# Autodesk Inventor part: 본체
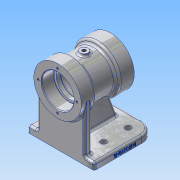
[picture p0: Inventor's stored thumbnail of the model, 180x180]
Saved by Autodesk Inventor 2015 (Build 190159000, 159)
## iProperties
Created: 2020-06
Part Number: 본체
Material: 알루미늄 6061
Document SubType Name: Modeling
Designer: user
Density: 2.7 g/cm^3
Appearance: 알루미늄 - 평지
Author: user
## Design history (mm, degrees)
sketch "스케치1"
  geometry: L1 (0, 49)-(90, 49); L2 (90, 49)-(90, -49); L3 (90, -49)-(0, -49); L4 (0, -49)-(0, 49); 2 further points
  constraints: 8 end point, 2 parallel, 1 coincident, 1 horizontal, 1 midpoint, 1 perpendicular
  dimensions: "d0" = 90 distance of L1.start L1.end; "d1" = 98 distance of L1.end L2.end
extrude "돌출1" new body sketch "스케치1" distance "d2" = 10; taper "d3" = 0 deg
sketch "스케치2"
  geometry: L1 (0, 0)-(-90, 0) reference; L2 (5, 80)-(-73, 80); L3 (0, 0)-(0, 10) reference; L4 (5, 80)-(-17, 80); L5 (-17, 80)-(-17, 115); L6 (-17, 115)-(5, 115); L7 (5, 115)-(5, 80); L8 (-73, 80)-(-51, 80); L9 (-51, 80)-(-51, 115); L10 (-51, 115)-(-73, 115); L11 (-73, 115)-(-73, 80); L12 (-17, 80)-(-51, 80); L13 (-51, 80)-(-51, 109); L14 (-51, 109)-(-17, 109); L15 (-17, 109)-(-17, 80); 1 further point
  constraints: 26 end point, 6 parallel, 4 horizontal, 3 perpendicular, 1 collinear, 1 midpoint
  dimensions: "d7" = 80 distance between parallel lines of L1 L2; "d8" = 78 distance of L2.start L2.end; "d9" = 5 distance from line of L3 L2.start; "d10" = 22 distance of L5.end L6.end; "d11" = 35 distance of L6.end L2.start; "d12" = 22 distance of L9.end L10.end; "d13" = 35 distance of L10.end L2.end; "d14" = 29 distance between parallel lines of L12 L14
revolve "회전1" sketch "스케치2" stored, may be unused: angle "d15" = 90 deg
sketch "스케치3"
  geometry: L1 (0, 49)-(0, -49) reference; L2 (90, -49)-(90, 49) reference; L3 (0, 35)-(10, 35); L4 (10, 35)-(10, -35); L5 (10, -35)-(0, -35); L6 (0, -35)-(0, 35); L7 (0, 5)-(78, 5); L8 (78, 5)-(78, -5); L9 (78, -5)-(0, -5); L10 (0, -5)-(0, 5); 2 further points
  constraints: 16 end point, 4 parallel, 3 midpoint, 2 horizontal, 2 perpendicular
  dimensions: "d16" = 70 distance of L3.end L4.end; "d17" = 10 distance of L3.start L3.end; "d18" = 10 distance of L7.end L8.end; "d19" = 12 distance between parallel lines of L2 L8
extrude "돌출2" join sketch "스케치3" stored distance "d20" = 70; taper "d21" = 0 deg
sketch "스케치4"
  geometry: L1 (90, -49)-(90, 49) reference; L2 (0, 5)-(78, 5); L3 (78, 5)-(78, -5); L4 (78, -5)-(0, -5); L5 (0, -5)-(0, 5); 2 further points
  constraints: 8 end point, 2 parallel, 1 coincident, 1 horizontal, 1 midpoint, 1 perpendicular
  dimensions: "d22" = 10 distance of L2.end L3.end; "d23" = 12 distance between parallel lines of L1 L3
extrude "돌출3" join sketch "스케치4" distance "d24" = 70; taper "d25" = 0 deg
feature "면 기울기1" dims angle "d26" = 20 deg
sketch "스케치5"
  geometry: L1 (5, 80)-(-73, 80); L2 (5, 45)-(5, 115) reference; L3 (-73, 45)-(-73, 115) reference; L4 (0, 0)-(-90, 0) reference; L5 (5, 80)-(-13, 80); L6 (-13, 80)-(-13, 103.2); L7 (-12.7, 103.5)-(5, 103.5); L8 (5, 103.5)-(5, 80); L9 (-73, 80)-(-55, 80); L10 (-55, 80)-(-55, 103.2); L11 (-55.3, 103.5)-(-73, 103.5); L12 (-73, 103.5)-(-73, 80); L13 (-13, 80)-(-19, 80); L14 (-19, 80)-(-19, 100); L15 (-19, 100)-(-13, 100); L16 (-13, 100)-(-13, 80); L17 (-19, 80)-(-49, 80); L18 (-49, 80)-(-49, 100); L19 (-46, 103)-(-22, 103); L20 (-19, 100)-(-19, 80); L21 (-49, 80)-(-55, 80); L22 (-55, 80)-(-55, 100); L23 (-55, 100)-(-49, 100); L24 (-49, 100)-(-49, 80); A1 r 0.3 centre (-12.7, 103.2) between (-12.7, 103.5) and (-13, 103.2); A2 r 0.3 centre (-55.3, 103.2) between (-55, 103.2) and (-55.3, 103.5); A3 r 3 centre (-22, 100) between (-19, 100) and (-22, 103); A4 r 3 centre (-46, 100) between (-46, 103) and (-49, 100); 4 further points
  constraints: 42 end point, 10 parallel, 8 point on circle, 8 point on line, 8 tangent, 6 horizontal, 5 perpendicular, 4 centre point, 2 midpoint, 1 collinear, 1 equal radius
  dimensions: "d27" = 80 distance between parallel lines of L4 L1; "d28" = 18 distance of point (-13, 103.5) L7.end; "d29" = 23.5 distance between parallel lines of L1 L7; "d30" = 18 distance of point (-55, 103.5) L11.end; "d31" = 23.5 distance of L9.end point (-55, 103.5); "d32" = 6 distance of L14.end L15.end; "d33" = 20 distance of L13.end L14.end; "d34" = 23 distance of L17.end point (-49, 103); "d35" = 30 distance of point (-49, 103) point (-19, 103); "d36" = 20 distance of L9.end L22.end; "d37" = 0.3 radius of A1; "d38" = 0.3 radius of A2; "d39" = 3 radius of A3
revolve "회전2" sketch "스케치5" stored, may be unused: angle "d40" = 90 deg
fillet "모깎기1" dims "d41" = 3
fillet "모깎기2" dims "d42" = 3
fillet "모깎기3" dims "d43" = 20
fillet "모깎기4" dims "d44" = 3
fillet "모깎기5" dims "d45" = 3
fillet "모깎기6" dims "d46" = 3
fillet "모깎기7" dims "d47" = 3
fillet "모깎기8" dims "d48" = 3
fillet "모깎기9" dims "d49" = 3
chamfer "모따기1" distance "d50" = 1; stored, may be unused: second distance "d51" = 2, angle "d52" = 45 deg
node "작업 평면1"
sketch "스케치6"
  geometry: L1 (-5, 35)-(-5, -35) reference; L2 (87, 29)-(87, -29) reference; C1 r 6 at (34, 0); 2 further points
  constraints: 1 centre point, 1 horizontal alignment, 1 midpoint
  dimensions: "d54" = 39 distance from line of L1 C1.centre; "d55" = 12 diameter of C1
extrude "돌출4" join sketch "스케치6" stored distance "d56" = 70; taper "d57" = 0 deg
hole "구멍1" diameter "d60" = 5.188; stored, may be unused: countersink angle "d64" = 90 deg, drill point angle "d66" = 0 deg; dims "d58" = 10, "d59" = 10, "d61" = 16, "d62" = 4, "d63" = 2, "d65" = 20
sketch "스케치7"
  geometry: C1 r 35 at (0, 0) reference; 2 further points
  constraints: 1 horizontal alignment
  dimensions: "d67" = 28.5 distance of C1.centre point (28.5, 0)
hole "구멍2" sketch "스케치7" at (28.5, 0) diameter "d68" = 3.242; stored, may be unused: countersink angle "d72" = 90 deg, drill point angle "d74" = 118 deg; dims "d69" = 10, "d70" = 4, "d71" = 2, "d73" = 12
node "작업 평면2"
fillet "모깎기10" dims "d78" = 3
sketch "스케치8"
  geometry: L1 (0, 0)-(-67, 0) reference; L2 (-70, 7)-(-70, 0) reference; 1 further point
  constraints: 1 other
  dimensions: "d79" = 4 distance from line of L1 point (-25, 4); "d80" = 45 distance from line of point (-25, 4) L2
feature "엠보싱1" sketch "스케치8" dims "d0" = 90, "d1" = 98, "d7" = 80, "d8" = 78, "d9" = 5, "d10" = 22, "d11" = 35, "d12" = 22, "d13" = 35, "d14" = 29, "d81" = 0.5, "d82" = 0
sketch "스케치9"
  geometry: L1 (90, -29)-(90, 29) reference; L2 (70, 49)-(0, 49) reference; 3 further points
  dimensions: "d83" = 20 distance from line of L1 point (70, 29); "d84" = 20 distance from line of L2 point (70, 29); "d85" = 36 distance of point (70, 29) point (34, 29); "d86" = 20 distance from line of point (34, 29) L2
hole "구멍3" sketch "스케치9" at (70, 29), (34, 29) diameter "d87" = 9; stored, may be unused: countersink angle "d91" = 90 deg, drill point angle "d93" = 118 deg; dims "d88" = 10, "d89" = 4, "d90" = 2, "d92" = 12
fillet "모깎기11" dims "d94" = 3
node "솔리드1"
pattern_circular "원형 패턴1" dims angle "d76" = 360 deg
mirror "대칭1"
mirror "대칭2"
other parameters: "d53" = 112
